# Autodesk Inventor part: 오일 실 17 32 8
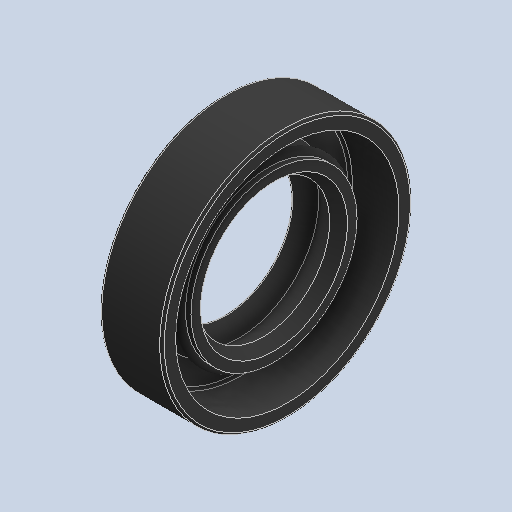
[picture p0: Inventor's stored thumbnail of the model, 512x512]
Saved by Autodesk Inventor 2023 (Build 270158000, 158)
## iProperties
Created: 2025-04
Part Number: 오일 실 17 32 8
Material: 고무
Description: 오일-실
Document SubType Name: Modeling
Designer: Admin
Density: 0.93 g/cm^3
Appearance: 기본값
Author: jhkim
Revision Number: 1
Sending System: Autodesk Inventor 2026
Preprocessor: ST-DEVELOPER v20.1
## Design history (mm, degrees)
feature "Solid1"
node "솔리드1"
